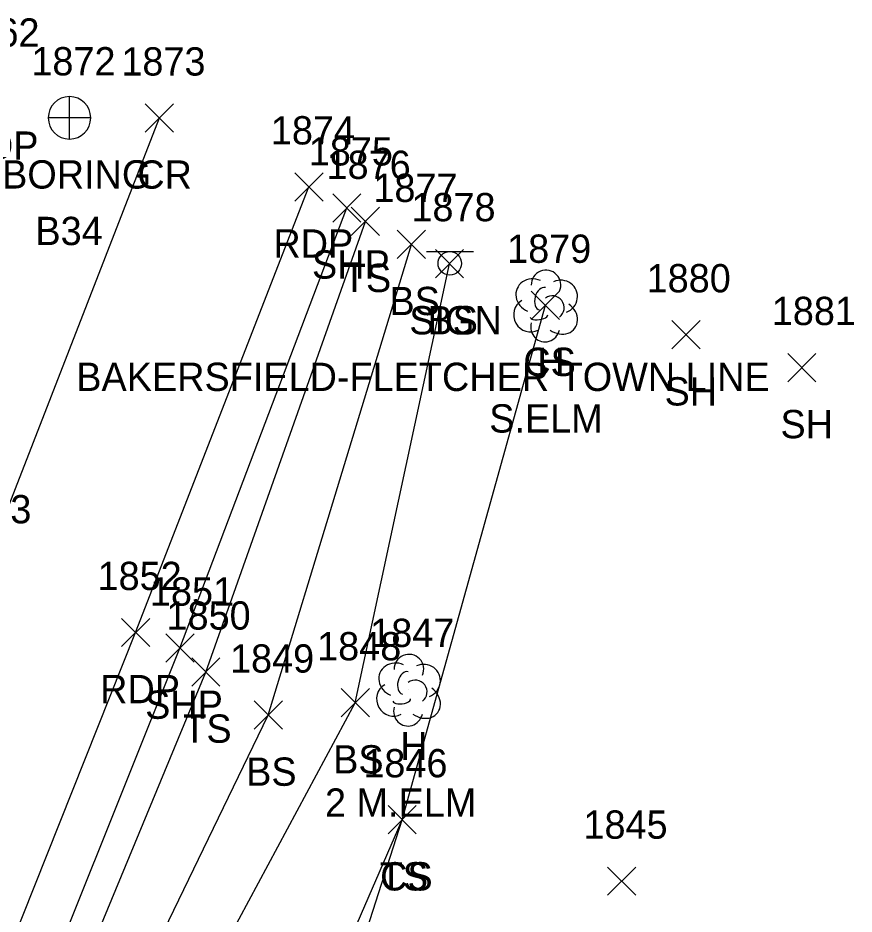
# Model space of a CAD drawing. Extents: x 1554917 to 1555870, y 813367 to 816333.
# Drawn here: x 1555332 to 1555391.2, y 814273.6 to 814337 of the extents above; entities that cross this region are included whole.
import ezdxf

# ---------------------------------------------------------------- set-up
doc = ezdxf.new("R2010")
doc.units = 0
for name, color, linetype in [('G_A', 7, 'Continuous'), ('G_C', 7, 'Continuous'), ('G_I', 7, 'Continuous'), ('GA_P', 7, 'Continuous'), ('L_A', 7, 'Continuous'), ('L_C', 7, 'Continuous'), ('L_I', 7, 'Continuous'), ('L_TIC', 7, 'Continuous'), ('LELB', 7, 'Continuous'), ('LTD', 7, 'Continuous'), ('P_A', 7, 'Continuous'), ('P_I', 7, 'Continuous'), ('P_TIC', 7, 'Continuous'), ('PET', 7, 'Continuous'), ('PRC', 7, 'Continuous'), ('PSP', 7, 'Continuous'), ('S_A', 7, 'Continuous'), ('S_C', 7, 'Continuous'), ('S_I', 7, 'Continuous'), ('SSGN', 7, 'Continuous')]:
    doc.layers.add(name, color=color, linetype=linetype)

msp = doc.modelspace()

# ---------------------------------------------------------------- linework, layer by layer
at = {"layer": 'GA_P'}
for p, q in [((1555335.671, 814329.936), (1555335.671, 814331.436)), ((1555335.671, 814329.936), (1555334.171, 814329.936)), ((1555337.171, 814329.936), (1555335.671, 814329.936)), ((1555335.671, 814328.436), (1555335.671, 814329.936))]:
    msp.add_line(p, q, dxfattribs=at)
for start, end in [(90, 180), (0, 90), (180, 270), (270, 0)]:
    msp.add_arc((1555335.671, 814329.936), 1.5, start, end, dxfattribs=at)
at = {"layer": 'L_TIC'}
for points in [[(1555355.598, 814321.616), (1555357.598, 814323.616)], [(1555357.598, 814321.616), (1555355.598, 814323.616)], [(1555358.856, 814319.986), (1555360.856, 814321.986)], [(1555360.856, 814319.986), (1555358.856, 814321.986)], [(1555361.546, 814318.623), (1555363.546, 814320.623)], [(1555363.546, 814318.623), (1555361.546, 814320.623)], [(1555368.323, 814315.683), (1555370.323, 814317.683)], [(1555370.323, 814315.683), (1555368.323, 814317.683)], [(1555378.266, 814313.596), (1555380.266, 814315.596)], [(1555380.266, 814313.596), (1555378.266, 814315.596)], [(1555386.462, 814311.281), (1555388.462, 814313.281)], [(1555388.462, 814311.281), (1555386.462, 814313.281)], [(1555344.313, 814289.75), (1555346.313, 814291.75)], [(1555346.313, 814289.75), (1555344.313, 814291.75)], [(1555354.877, 814287.577), (1555356.877, 814289.577)], [(1555356.877, 814287.577), (1555354.877, 814289.577)], [(1555348.725, 814286.708), (1555350.725, 814288.708)], [(1555350.725, 814286.708), (1555348.725, 814288.708)], [(1555358.199, 814279.306), (1555360.199, 814281.306)], [(1555360.199, 814279.306), (1555358.199, 814281.306)], [(1555358.199, 814279.306), (1555360.199, 814281.306)], [(1555360.199, 814279.306), (1555358.199, 814281.306)], [(1555373.711, 814274.965), (1555375.711, 814276.965)], [(1555375.711, 814274.965), (1555373.711, 814276.965)]]:
    msp.add_lwpolyline(points, dxfattribs=at)
at = {"layer": 'LELB'}
for points in [[(1555341.697, 814160.964), (1555323.872, 814155.259), (1555306.258, 814148.834), (1555294.408, 814144.193), (1555291.449, 814143.718), (1555289.043, 814144.156), (1555287.978, 814146.105), (1555302.244, 814181.575), (1555311.889, 814207.745), (1555329.494, 814252.618), (1555345.313, 814290.75), (1555356.598, 814322.616)], [(1555291.015, 814145.475), (1555290.777, 814144.989), (1555289.945, 814146.121), (1555305.559, 814180.39), (1555315.681, 814205.134), (1555332.519, 814252.127), (1555349.725, 814287.708), (1555359.856, 814320.986)], [(1555291.015, 814145.475), (1555308.798, 814178.88), (1555319.937, 814204.008), (1555335.363, 814250.393), (1555355.877, 814288.577), (1555362.546, 814319.623)], [(1555318.119, 814171.985), (1555328.118, 814196.586), (1555348.861, 814248.084), (1555359.199, 814280.306), (1555369.323, 814316.683)], [(1555345.753, 814249.363), (1555359.199, 814280.306)]]:
    msp.add_lwpolyline(points, dxfattribs=at)
at = {"layer": 'LTD'}
for p, q in [((1555369.323, 814316.683), (1555369.323, 814316.683)), ((1555369.323, 814316.683), (1555369.323, 814316.683)), ((1555359.63, 814289.521), (1555359.63, 814289.521)), ((1555359.63, 814289.521), (1555359.63, 814289.521))]:
    msp.add_line(p, q, dxfattribs=at)
for centre in [(1555369.37, 814318.117), (1555359.677, 814290.955)]:
    msp.add_arc(centre, 1.047, 335.52715, 180.95627, dxfattribs=at)
for centre, major_axis, ratio, start_param, end_param in [((1555368.531, 814317.35), (1.21, -0.512), 0.895232, 1.570796, 4.712389), ((1555370.365, 814317.267), (-1.141, -0.483), 0.949671, 1.570796, 4.712389), ((1555369.115, 814317.142), (-0.208, -0.792), 0.645439, 3.141593, 6.283185), ((1555369.823, 814316.517), (-0.5, 0.667), 0.989748, 3.141593, 6.283185), ((1555368.24, 814315.975), (0.584, -1.042), 0.959034, 3.141593, 6.283185), ((1555370.323, 814315.85), (-1.09, 0.792), 0.841452, 1.570796, 4.712389), ((1555368.865, 814315.933), (-0.625, -0.083), 0.423636, 0, 3.141593), ((1555369.323, 814315.183), (0.265, 1.061), 0.942809, 1.570796, 4.712389), ((1555358.838, 814290.187), (1.21, -0.512), 0.895232, 1.570796, 4.712389), ((1555360.671, 814290.104), (-1.141, -0.483), 0.949671, 1.570796, 4.712389), ((1555359.421, 814289.979), (-0.208, -0.792), 0.645439, 3.141593, 6.283185), ((1555360.13, 814289.354), (-0.5, 0.667), 0.989748, 3.141593, 6.283185), ((1555358.547, 814288.812), (0.584, -1.042), 0.959034, 3.141593, 6.283185), ((1555360.63, 814288.688), (-1.09, 0.792), 0.841452, 1.570796, 4.712389), ((1555359.172, 814288.771), (-0.625, -0.083), 0.423636, 0, 3.141593), ((1555359.63, 814288.021), (0.265, 1.061), 0.942809, 1.570796, 4.712389)]:
    msp.add_ellipse(centre, major_axis=major_axis, ratio=ratio, start_param=start_param, end_param=end_param, dxfattribs=at)
at = {"layer": 'P_TIC'}
for points in [[(1555341.034, 814328.925), (1555343.034, 814330.925)], [(1555343.034, 814328.925), (1555341.034, 814330.925)], [(1555351.605, 814324.053), (1555353.605, 814326.053)], [(1555353.605, 814324.053), (1555351.605, 814326.053)], [(1555354.287, 814322.567), (1555356.287, 814324.567)], [(1555356.287, 814322.567), (1555354.287, 814324.567)], [(1555339.351, 814292.545), (1555341.351, 814294.545)], [(1555341.351, 814292.545), (1555339.351, 814294.545)], [(1555342.486, 814291.443), (1555344.486, 814293.443)], [(1555344.486, 814291.443), (1555342.486, 814293.443)]]:
    msp.add_lwpolyline(points, dxfattribs=at)
at = {"layer": 'PET'}
msp.add_lwpolyline([(1555182.568, 813892.252), (1555203.697, 813945.015), (1555216.848, 813978.344), (1555228.718, 814008.852), (1555239.472, 814035.465), (1555248.637, 814059.877), (1555262.917, 814096.005), (1555276.683, 814131.303), (1555286.362, 814156.334), (1555297.108, 814184.041), (1555306.669, 814209.508), (1555324.283, 814253.264), (1555340.351, 814293.545), (1555352.605, 814325.053)], dxfattribs=at)
at = {"layer": 'PRC'}
msp.add_lwpolyline([(1554976.762, 813382.178), (1554992.841, 813427.905), (1555014.068, 813486.005), (1555030.624, 813532.308), (1555046.369, 813573.085), (1555064.69, 813621.189), (1555082.406, 813667.527), (1555112.105, 813744.097), (1555110.691, 813739.792), (1555136.162, 813805.735), (1555152.521, 813846.933), (1555172.027, 813896.178), (1555193.956, 813951.204), (1555206.369, 813983.398), (1555218.126, 814013.217), (1555228.646, 814039.26), (1555237.929, 814064.306), (1555252.221, 814099.758), (1555265.8, 814135.892), (1555275.258, 814160.086), (1555297.17, 814214.772), (1555313.827, 814257.943), (1555329.72, 814298.264), (1555342.034, 814329.925)], dxfattribs=at)
at = {"layer": 'PSP'}
msp.add_lwpolyline([(1555197.674, 813922.422), (1555211.908, 813956.86), (1555220.23, 813977.153), (1555231.802, 814008.205), (1555242.477, 814034.479), (1555251.859, 814058.973), (1555266.043, 814094.805), (1555272.786, 814112.73), (1555286.228, 814147.196), (1555300.195, 814183.09), (1555310.337, 814208.216), (1555327.376, 814252.3), (1555343.486, 814292.443), (1555355.287, 814323.567)], dxfattribs=at)
at = {"layer": 'SSGN'}
for p, q in [((1555360.919, 814320.476), (1555364.252, 814320.476)), ((1555362.566, 814319.643), (1555362.566, 814319.643))]:
    msp.add_line(p, q, dxfattribs=at)
msp.add_circle((1555362.566, 814319.643), 0.833, dxfattribs=at)

# ---------------------------------------------------------------- texts
at = {"layer": 'G_A'}
msp.add_text('BORING', height=2, dxfattribs=at).set_placement((1555330.907, 814324.936))
at = {"layer": 'G_C'}
msp.add_text('B34', height=2, dxfattribs=at).set_placement((1555333.262, 814320.936))
at = {"layer": 'G_I'}
msp.add_text('1872', height=2, dxfattribs=at).set_placement((1555332.978, 814332.936))
at = {"layer": 'L_A'}
for s, p in [('TS', (1555355.007, 814317.616)), ('BS', (1555358.297, 814315.986)), ('BS', (1555360.987, 814314.623)), ('CS', (1555367.764, 814311.683)), ('H', (1555368.756, 814311.683)), ('SH', (1555377.754, 814309.596)), ('SH', (1555385.95, 814307.281)), ('TS', (1555343.722, 814285.75)), ('H', (1555359.063, 814284.521)), ('BS', (1555354.318, 814283.577)), ('BS', (1555348.166, 814282.708)), ('TS', (1555357.609, 814275.306)), ('CS', (1555357.64, 814275.306))]:
    msp.add_text(s, height=2, dxfattribs=at).set_placement(p)
at = {"layer": 'L_C'}
for s, p in [('S.ELM', (1555365.355, 814307.683)), ('2 M.ELM', (1555353.74, 814280.521))]:
    msp.add_text(s, height=2, dxfattribs=at).set_placement(p)
at = {"layer": 'L_I'}
for s, p in [('1876', (1555353.85, 814325.616)), ('1877', (1555357.163, 814323.986)), ('1878', (1555359.853, 814322.623)), ('1879', (1555366.622, 814319.683)), ('1879', (1555366.622, 814319.683)), ('1880', (1555376.486, 814317.596)), ('1881', (1555385.336, 814315.281)), ('1850', (1555342.533, 814293.75)), ('1847', (1555356.937, 814292.521)), ('1848', (1555353.184, 814291.577)), ('1849', (1555347.024, 814290.708)), ('1846', (1555356.451, 814283.306)), ('1846', (1555356.451, 814283.306)), ('1845', (1555372.018, 814278.965))]:
    msp.add_text(s, height=2, dxfattribs=at).set_placement(p)
at = {"layer": 'P_A'}
for s, p in [('RDP', (1555327.833, 814326.97)), ('CR', (1555340.467, 814324.925)), ('RDP', (1555350.093, 814320.053)), ('SHP', (1555352.822, 814318.567)), ('RDP', (1555337.839, 814288.545)), ('SHP', (1555341.022, 814287.443))]:
    msp.add_text(s, height=2, dxfattribs=at).set_placement(p)
at = {"layer": 'P_I'}
for s, p in [('1862', (1555327.604, 814334.97)), ('1873', (1555339.341, 814332.925)), ('1874', (1555349.912, 814328.053)), ('1875', (1555352.594, 814326.567)), ('1853', (1555327.027, 814301.264)), ('1852', (1555337.658, 814296.545)), ('1851', (1555341.36, 814295.443))]:
    msp.add_text(s, height=2, dxfattribs=at).set_placement(p)
at = {"layer": 'S_A'}
msp.add_text('SIGN', height=2, dxfattribs=at).set_placement((1555359.704, 814314.623))
at = {"layer": 'S_C'}
msp.add_text('BAKERSFIELD-FLETCHER TOWN LINE', height=2, dxfattribs=at).set_placement((1555336.153, 814310.623))
at = {"layer": 'S_I'}
msp.add_text('1878', height=2, dxfattribs=at).set_placement((1555359.853, 814322.623))

doc.saveas('drawing.dxf')
